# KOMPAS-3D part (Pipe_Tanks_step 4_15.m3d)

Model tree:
1. X Axis
2. Y Axis
3. Z Axis  (labels: T-Bend Dn 150; Pipe Dn 150; Bend 90 Dn 150)
     Òîëùèíà ñòåíêè 1 = 1

Referenced files in C:\Documents and Settings\kashirsky\Мои документы\Camtasia Studio\Pipelines3D\Tanks\: Tanks_step 4.a3d
Referenced files in C:\Program Files\ASCON\KOMPAS-3D V10\Libs\Piping\LOAD\: Piping_C_Pipe_150_1000.m3d
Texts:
  Pipe Dn 150
  Steel ASTM A295
  Three Point Plane
  Plane at Angle
  Line and Point Plane
  Axis through Two Vertices
  Axis of Feature
  Axis of Conical Surface
  Axis through Edge
  Trim by Surface
  Trim by Sketch
  Feature with No History
  Intersection Axis of Two Planes
  Two Line Plane
  Line and Face Plane
  Bend by line
  Hole in sheet body
  Cut in sheet body
  Point in CM
  Linear Dimension from Line to Point
  Surface Finish Symbol
  Geometric Tolerance Symbol
  Leader #1
  Leader #2
  Leader #3
  Shape Deviations and Datum
  Node point number
  Mark of coordination axis
  Node point designation
  Mark/Reference designation with leader
  Mark/reference designation on line
  Mark/Reference designation without leader
  T-Bend Dn 150
  Bend 90 Dn 150
  Plane of section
